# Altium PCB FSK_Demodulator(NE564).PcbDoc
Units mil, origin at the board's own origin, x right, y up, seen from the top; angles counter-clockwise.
Board outline 6000 x 4000 mil, 2 copper layers (Top Layer, Bottom Layer); 20 components, 17 nets, 56 pads, 0 vias.
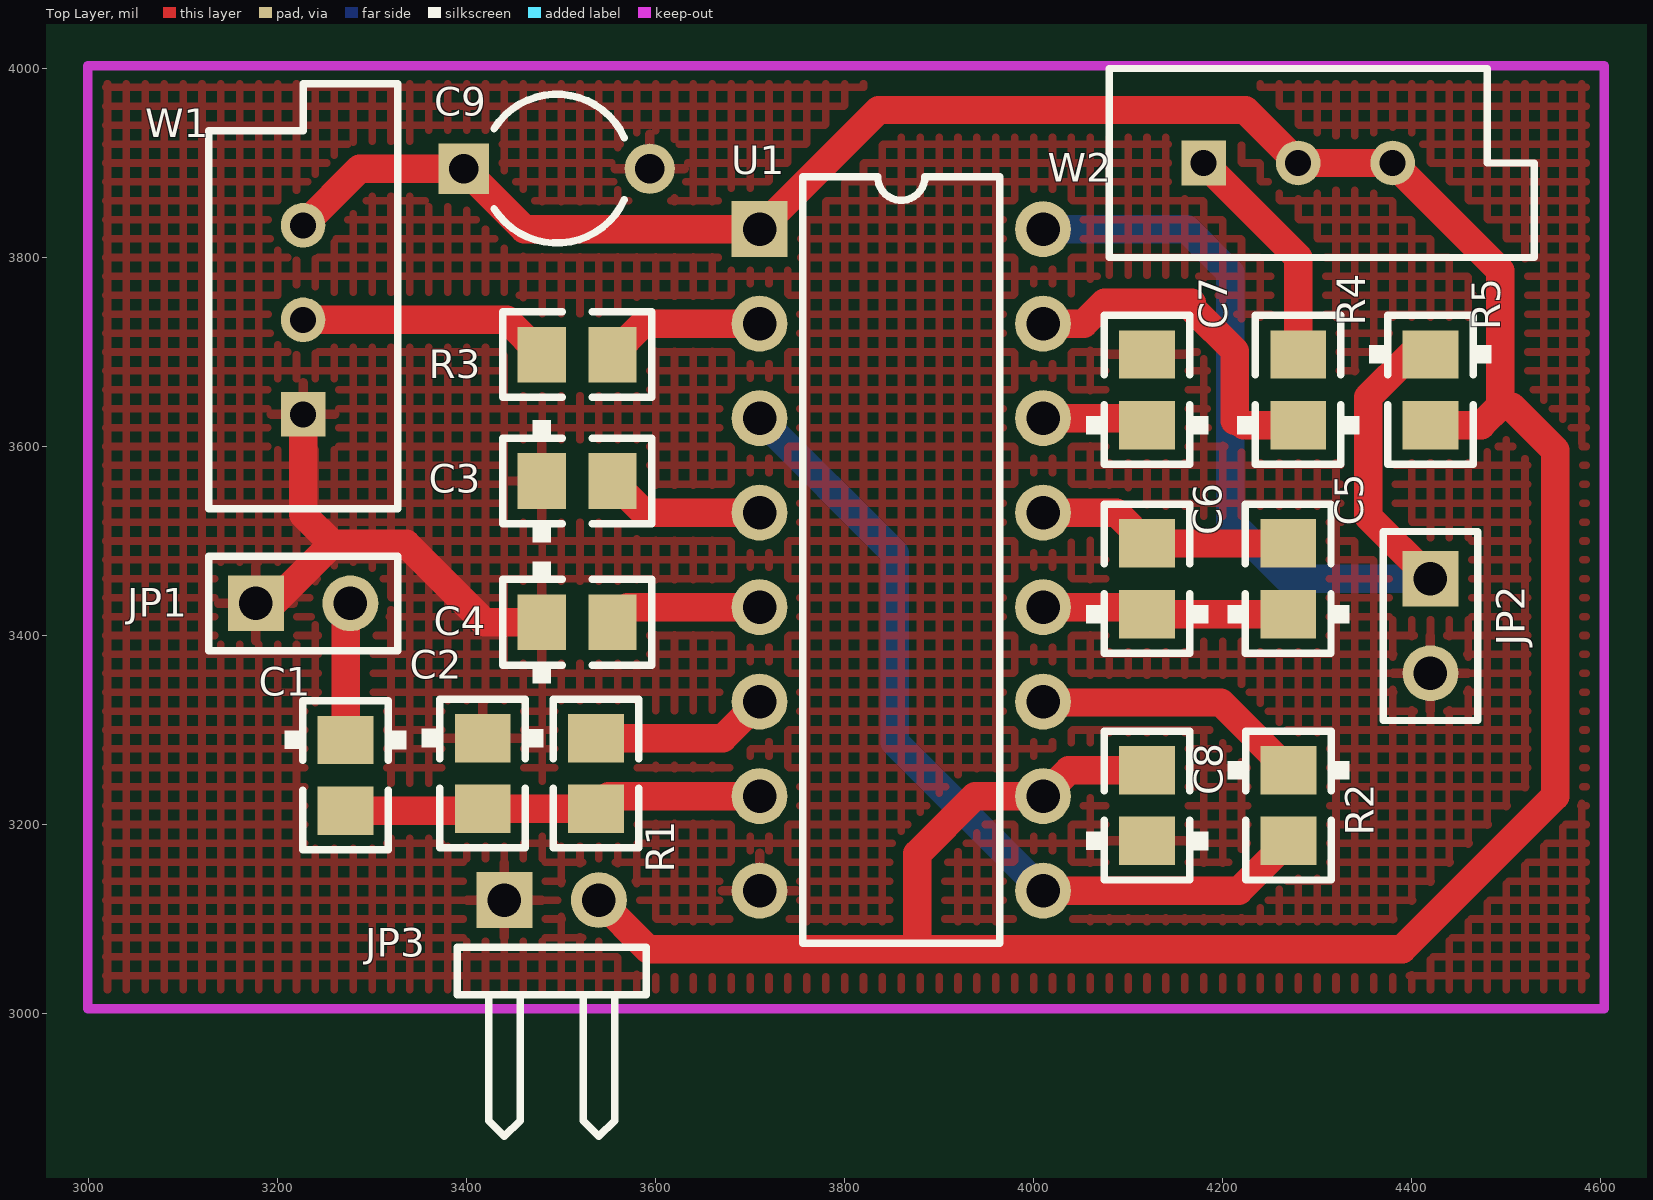
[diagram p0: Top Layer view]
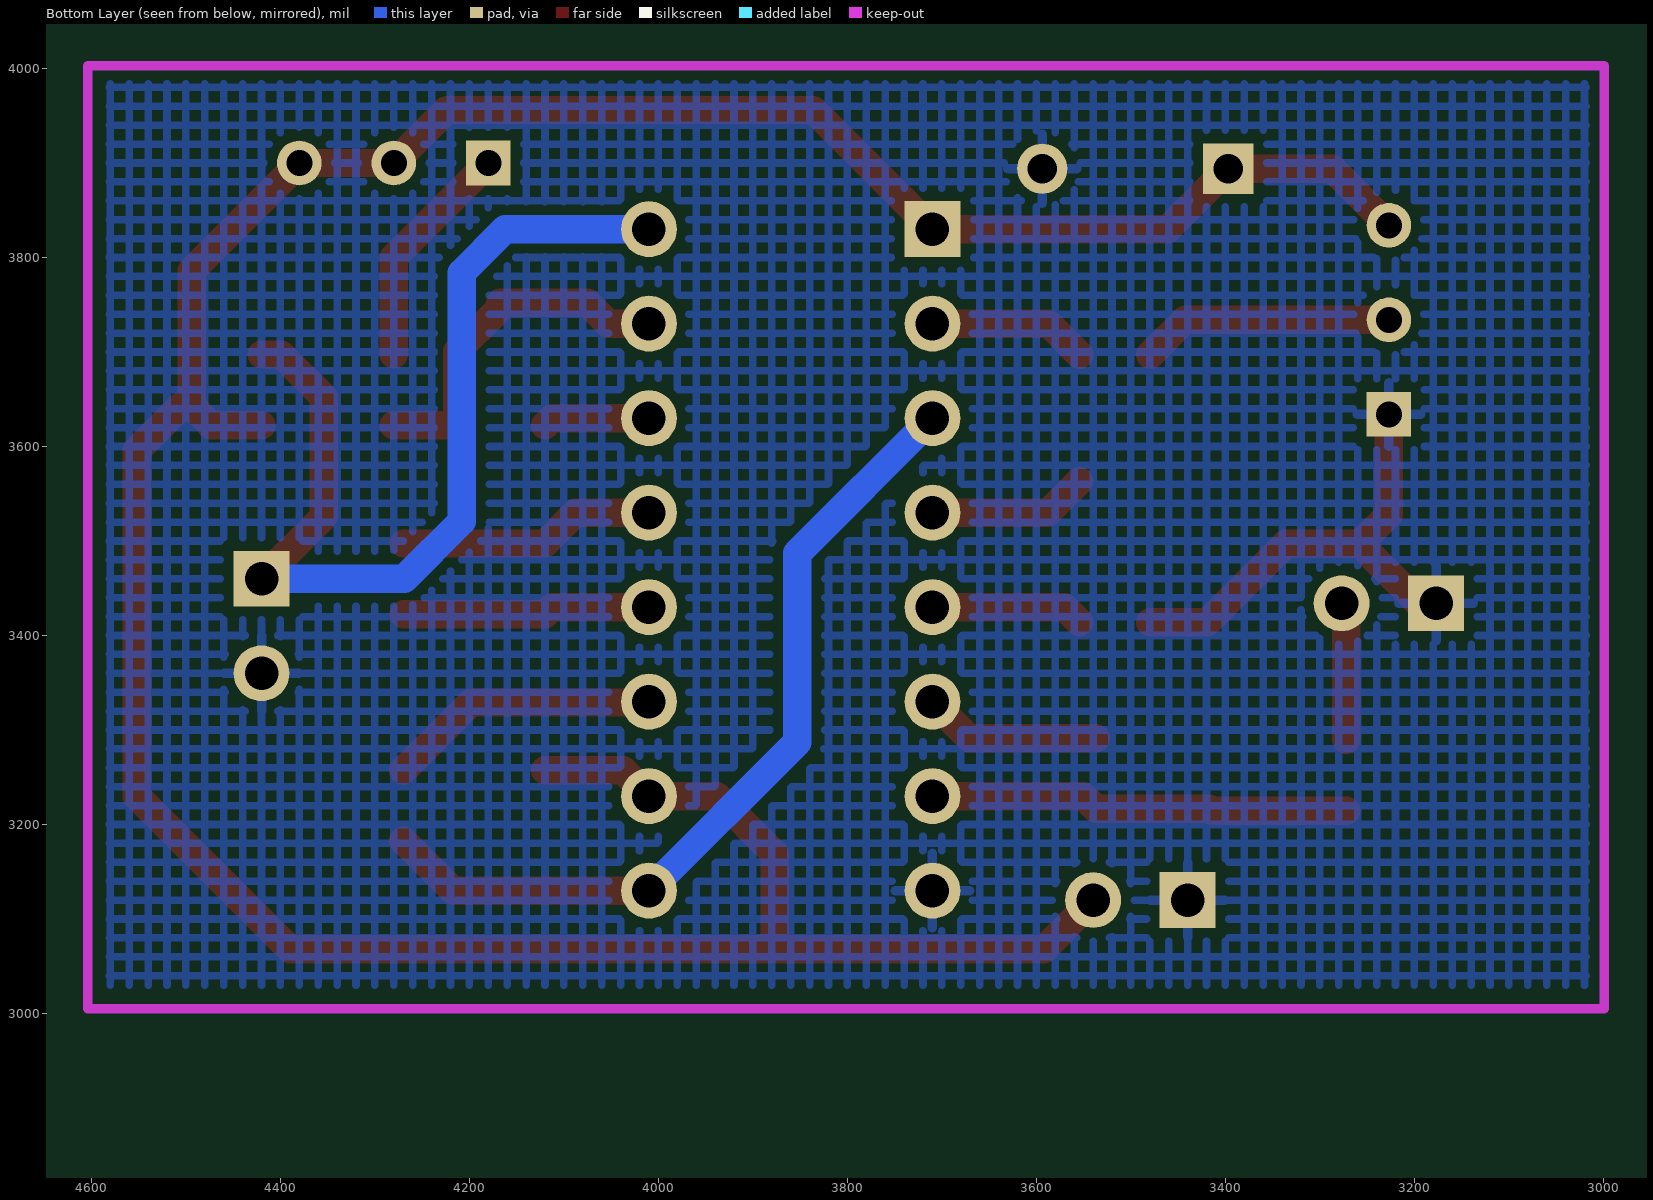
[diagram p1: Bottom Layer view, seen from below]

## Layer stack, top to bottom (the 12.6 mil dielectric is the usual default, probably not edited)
Top Layer: signal copper 1.4
Dielectric: dielectric 12.6, FR-4, Dk 4.8
Bottom Layer: signal copper 1.4

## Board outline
1000,1000 7000,1000 7000,5000 1000,5000

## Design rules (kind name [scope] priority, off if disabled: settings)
Clearance [All] p1: gap=10
ComponentClearance [All] p1: gap=10 collisioncheckmode=0
PolygonConnect [All] p1: connectstyle=Relief reliefconductorwidth=10 reliefentries=4 polygonreliefangle="90 Angle"
RoutingLayers [All] p1: top layer=Horizontal bottom layer=Vertical
RoutingVias [All] p1: holewidth=28 width=50 viastyle="Through Hole" minholewidth=28 minwidth=50 maxholewidth=28 maxwidth=50
SolderMaskExpansion [All] p1: expansion=4
TestPointUsage [All] p1: valid=0 allowmultiple=FALSE
Testpoint [All] p1: side=15 testpointundercomponent=TRUE minsize=40 maxsize=100 preferedsize=60 minholesize=0 maxholesize=40 preferedholesize=32 testpointgrid=1 style=1023 order=-539222988
Width Width_2 [InNet('+5')] p1: maxlimit=50 minlimit=15 preferedwidth=30
Width Width_1 [InNet('GND')] p2: maxlimit=50 minlimit=15 preferedwidth=30
Width [All] p3: maxlimit=50 minlimit=10 preferedwidth=30
16 further rules are at their usual default settings.

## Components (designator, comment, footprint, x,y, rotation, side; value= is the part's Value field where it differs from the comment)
C1 "100pF" CC2012-0805 3272,3252 r270 top
C2 "100pF" CC2012-0805 3417,3254 r270 top
C3 "300pF" CC2012-0805 3517,3563.45 r0 top
C4 "300pF" CC2012-0805 3517,3414 r0 top
C5 "47pF" CC2012-0805 4269.44,3460 r90 top
C6 "5-20pF" CC2012-0805 4120,3460 r90 top
C7 "100pF" CC2012-0805 4119.95,3660 r90 top
C8 "100pF" CC2012-0805 4119.94,3220 r90 top
C9 "100uF" CAPR5-4X5 3397,3894 r0 top
JP1 "Header 2" HDR1X2 3177,3434 r0 top
JP2 "Header 2" HDR1X2 4420,3460 r270 top
JP3 "Header 2H" HDR1X2H 3440,3120 r0 top
R1 "1K" R2012-0805 3537,3254 r90 top
R2 "200" CC2012-0805 4269.91,3220 r270 top
R3 "2K" R2012-0805 3517,3697.16 r0 top
R4 "2K" CC2012-0805 4280,3660 r90 top
R5 "1.2K" CC2012-0805 4420,3660 r270 top
U1 "NE564" DIP-16 3860,3480 r270 top
W1 "10K" VR5 3227,3734 r90 top
W2 "10K" VR5 4280,3900 r0 top

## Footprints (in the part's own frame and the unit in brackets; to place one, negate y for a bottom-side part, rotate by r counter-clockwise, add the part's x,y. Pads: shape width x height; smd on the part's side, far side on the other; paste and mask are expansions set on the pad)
CAPR5-4X5 [mm]
  rect 1.35x1.35 hole 0.8: 1(0,0)
  round 1.35 hole 0.8: 2(5,0)
  silkscreen extent 0.81,-2 4.32,2
CC2012-0805 [mm]
  rect 1.3x1.5 smd: 1(-0.95,0) 2(0.95,0)
  silkscreen extent -2,-1.65 2,1.64
DIP-16 [mm]
  rect 1.5x1.5 hole 0.9: 1(-8.89,-3.81)
  round 1.5 hole 0.9: 2(-6.35,-3.81) 3(-3.81,-3.81) 4(-1.27,-3.81) 5(1.27,-3.81) 6(3.81,-3.81) 7(6.35,-3.81) 8(8.89,-3.81) 9(8.89,3.81) 10(6.35,3.81) 11(3.81,3.81) 12(1.27,3.81) 13(-1.27,3.81) 14(-3.81,3.81) 15(-6.35,3.81) 16(-8.89,3.81)
  silkscreen extent -10.3,-2.65 10.3,2.65
HDR1X2 [mm]
  rect 1.5x1.5 hole 0.9: 1(0,0)
  round 1.5 hole 0.9: 2(2.54,0)
  silkscreen extent -1.27,-1.27 3.81,1.27
HDR1X2H [mm]
  rect 1.5x1.5 hole 0.9: 1(0,0)
  round 1.5 hole 0.9: 2(2.54,0)
  silkscreen extent -1.27,-6.35 3.81,-1.27
R2012-0805 [mm]
  rect 1.3x1.5 smd: 1(-0.95,0) 2(0.95,0)
  silkscreen extent -2,-1.15 2,1.15
VR5 [mm]
  rect 1.2x1.2 hole 0.7: 1(-2.54,0)
  round 1.2 hole 0.7: 2(0,0) 3(2.54,0)
  silkscreen extent -5.08,-2.54 6.35,2.54

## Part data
C1 C2 C3 C4 C5 C7 C8: library part Cap, "Capacitor"
C6: library part "Cap Var", "Variable or Adjustable Capacitor"
C9: library part Cap2, "Capacitor"
JP1 JP2: "Header, 2-Pin"
JP3: "Header, 2-Pin,  Right Angle"
R1 R2 R3 R4 R5: library part Res1, "Resistor"
W1 W2: library part RPot1, "Potentiometer"

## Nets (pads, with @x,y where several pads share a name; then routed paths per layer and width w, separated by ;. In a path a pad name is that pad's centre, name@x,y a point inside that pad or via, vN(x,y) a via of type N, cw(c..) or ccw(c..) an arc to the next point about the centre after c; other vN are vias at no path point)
+5: C8.2 C9.1 JP3.2 R5.2 U1.1 U1.10 W1.3 W2.2 W2.3 | length 3578.7
  Top Layer w30: W1.3 3287,3894 C9.1 3461,3830 U1.1 3836,3956 4224,3956 W2.2 W2.3 4494,3786 4494,3643 4473.6,3622.6 R5.2 ; JP3.2 3592,3068 4390,3068 4552,3230 4552,3596 4506,3642 ; 3877,3068 3877,3169 3938,3230 U1.10 4037.4,3257.4 C8.2
GND: C2.1 C3.1 C4.1 C7.2 C8.1 C9.2 JP1.1 JP2.2 JP3.1 U1.8 W1.1 | length 512.9
  Top Layer w30: JP1.1 3195,3434 3258,3497 ; W1.1 3227,3528 3258,3497 ; C4.1 3419,3414 3336,3497 3258,3497
NetC1_1: C1.1 JP1.2 | length 146.7
  Top Layer w30: C1.1 3272,3429 JP1.2
NetC1_2: C1.2 C2.2 R1.1 U1.7 | length 444.4
  Top Layer w30: C1.2 3415,3214.6 C2.2 R1.1 3550.4,3230 U1.7
NetC3_2: C3.2 U1.4 | length 169.5
  Top Layer w30: C3.2 3587.85,3530 U1.4
NetC4_2: C4.2 U1.5 | length 162.2
  Top Layer w30: C4.2 3570.4,3430 U1.5
NetC5_1: C5.1 C6.1 U1.12 | length 262.5
  Top Layer w30: U1.12 4112.6,3430 C6.1 C5.1
NetC5_2: C5.2 C6.2 U1.13 | length 272.9
  Top Layer w30: U1.13 4087.4,3530 C6.2 C5.2
NetC7_1: C7.1 U1.14 | length 113
  Top Layer w30: U1.14 4112.54,3630 C7.1
NetJP2_1: JP2.1 R5.1 U1.16 | length 1021.5
  Top Layer w30: JP2.1 4354,3526 4354,3652 4399.4,3697.4 R5.1
  Bottom Layer w30: U1.16 4162,3830 4208,3784 4208,3521 4269,3460 JP2.1
NetR1_2: R1.2 U1.6 | length 189
  Top Layer w30: R1.2 3671.4,3291.4 U1.6
NetR2_1: R2.1 U1.11 | length 297.6
  Top Layer w30: U1.11@4002,3329 4198.31,3329 R2.1
NetR2_2: R2.2 U1.3 U1.9 | length 906
  Top Layer w30: U1.9 4217.31,3130 R2.2
  Bottom Layer w30: U1.3 3853,3487 3853,3287 U1.9
NetR3_1: R3.1 W1.2 | length 267.9
  Top Layer w30: W1.2 3442.76,3734 R3.1
NetR3_2: R3.2 U1.2 | length 169.2
  Top Layer w30: R3.2 3587.24,3730 U1.2
NetR4_1: R4.1 U1.15 | length 358.9
  Top Layer w30: U1.15 4053,3730 4075,3752 4167.4,3752 ; 4170,3744 4213,3701 4213,3627 ; 4222.4,3622.6 R4.1
NetR4_2: R4.2 W2.1 | length 244
  Top Layer w30: W2.1 4280,3800 R4.2

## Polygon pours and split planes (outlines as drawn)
GND on Top Layer (hatched 90Degree grid 20 track 8, remove dead copper): 3011,3987 3011,3025 4592,3025 4592,3991 3009,3991
GND on Bottom Layer (hatched 90Degree grid 20 track 8, remove dead copper): 3015,3982 3015,3030 4581,3030 4581,3993 3019,3993 3019,3985

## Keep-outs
Keep-Out Layer:
  lines w10: 2999,3005 4604,3005 4604,4003 2999,4003 2999,3005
